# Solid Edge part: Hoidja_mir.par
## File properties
Author: Türk
Template: Iso Part.par
Last saved by: Türk
Revision: 2
Application: Solid Edge
Accuracy: 0,990
Username: Türk
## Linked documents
Hoidja.par
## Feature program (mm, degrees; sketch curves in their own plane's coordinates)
part copy "CopiedPart_1"
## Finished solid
Body 1: solid body, 45 faces, 105 edges, 58 vertices.
  Faces by surface: plane 25, cylinder 18, torus 2
  Edges by curve: line 69, circle 36
Bounding box of the edges (mm; curved faces can reach further): 221.000 x 108.000 x 233.000, from (-181, -108, -134) to (40, 0, 99).
Cylindrical faces by radius (mm): R4 x3, R5 x1, R10 x3, R10.5 x4, R18 x1, R25 x2, R30 x1, R32.5 x1, R40 x2
Toroidal faces (ring radius, tube radius in mm): R10.5 r2.5 x2
Planar faces by outward normal: +x 3, +y 2, +z 4, -x 4, -y 2, -z 4, oblique 6
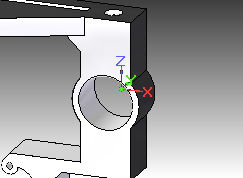
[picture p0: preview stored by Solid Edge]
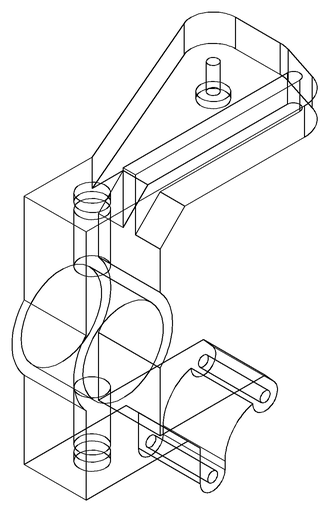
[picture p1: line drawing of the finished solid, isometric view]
